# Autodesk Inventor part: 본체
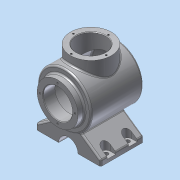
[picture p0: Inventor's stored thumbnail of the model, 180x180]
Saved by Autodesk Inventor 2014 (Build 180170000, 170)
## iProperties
Created: 2017-04
Part Number: 본체
Material: 알루미늄 6061
Document SubType Name: Modeling
Designer: SCD-A15
Density: 2.71 g/cm^3
Appearance: 알루미늄 - 평지
Mass: 1670.64 g
Surface Area: 1066.86 cm^2
Volume: 616.472 cm^3
Author: SCD-A15
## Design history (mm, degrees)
sketch "스케치1"
  geometry: L1 (-60, 0)-(60, 0); L2 (-45, 50)-(46.454, 50); L3 (-48, 47)-(-48, 41); L4 (-51, 38)-(-60, 38); L5 (-60, 38)-(-60, 28); L6 (-38, 37)-(-38, 27); L7 (-35, 40)-(39.903, 40); L8 (-38, 27)-(-59, 27); L9 (-60, 28)-(-59, 27); A1 r 113 centre (-53, 0) between (60, 0) and (49.166, 48.282); A2 r 103 centre (-53, 0) between (50, 0) and (42.69, 38.11); A3 r 3 centre (-35, 37) between (-35, 40) and (-38, 37); A4 r 3 centre (39.903, 37) between (42.69, 38.11) and (39.903, 40); A5 r 3 centre (46.454, 47) between (49.166, 48.282) and (46.454, 50); A6 r 3 centre (-45, 47) between (-45, 50) and (-48, 47); A7 r 3 centre (-51, 41) between (-51, 38) and (-48, 41); 6 further points
  constraints: 18 end point, 16 point on circle, 10 point on line, 10 tangent, 7 centre point, 4 equal radius, 4 parallel, 3 perpendicular, 1 horizontal
  dimensions: "d0" = 120 distance of L1.start L1.end; "d1" = 226 diameter of A1; "d2" = 100 diameter of L2 L1; "d4" = 10 radial gap between concentric circles of A2 A1; "d7" = 60 horizontal distance of point (0, 0) L4.end; "d8" = 22 distance between parallel lines of L5 L6; "d9" = 54 diameter of L8 L1; "d10" = 76 diameter of L4.end L1; "d12" = 108 horizontal distance of point (-48, 50) L1.end; "d13" = 3 radius of A3; "d14" = 1 distance of L5.end point (-60, 27); "d15" = 1 distance of L8.end point (-60, 27) (= d14); "d98" = 80 diameter of L7 L1
revolve "회전1" sketch "스케치1" stored, may be unused: angle "d16" = 90 deg
node "작업 평면1"
sketch "스케치2"
  geometry: C1 r 27 at (-2, 0); C2 r 38 at (-2, 0); 3 further points
  constraints: 2 centre point, 2 coincident, 1 vertical alignment, 2 other
extrude "돌출1" join sketch "스케치2" stored distance "d21" = 10; taper "d22" = 0 deg
extrude "돌출2" cut sketch "스케치2" distance "d23" = 50; taper "d24" = 0 deg
hole "구멍1" sketch "스케치2" diameter "d25" = 3.242; stored, may be unused: countersink angle "d29" = 90 deg, drill point angle "d31" = 118 deg; dims "d26" = 8, "d27" = 4, "d28" = 2, "d30" = 10
sketch "스케치3"
  geometry: L1 (-82, -60)-(-72, -60); L2 (-72, -60)-(-45.101, -21.584); L3 (-72, -60)-(-25.103, -60); L4 (-82, 60)-(-72, 60); L5 (-72, 60)-(-45.101, 21.584); L6 (-72, 60)-(-25.103, 60); L7 (-82, -60)-(-82, -18); L8 (-82, 18)-(-82, 60); A1 r 18 centre (-82, 0) between (-82, -18) and (-82, 18); A2 r 50 centre (0, 0) between (-45.101, 21.584) and (-45.101, -21.584); 1 further point
  constraints: 16 end point, 4 point on circle, 2 centre point, 2 equal length, 2 horizontal, 2 perpendicular, 1 parallel
  dimensions: "d36" = 120 distance of L1.start L4.start; "d38" = 10 distance of L1.start L1.end; "d39" = 55 deg angle of L3 L2; "d40" = 10 distance of L4.start L4.end; "d41" = 55 deg angle of L5 L6; "d42" = 36 diameter of A1; "d43" = 82 distance of point (0, 0) A1.centre
extrude "돌출3" join sketch "스케치3" stored distance "d44" = 80; taper "d45" = 0 deg
node "작업 평면2"
sketch "스케치4"
  geometry: L1 (12, -68)-(12, -78); L2 (12, -78)-(28, -78); L3 (28, -78)-(28, -68); L4 (52, -68)-(52, -78); L5 (52, -78)-(68, -78); L6 (68, -78)-(68, -68); L7 (12, 32)-(12, 42); L8 (12, 42)-(28, 42); L9 (28, 42)-(28, 32); L10 (52, 32)-(52, 42); L11 (52, 42)-(68, 42); L12 (68, 42)-(68, 32); A1 r 8 centre (20, -68) between (28, -68) and (12, -68); A2 r 8 centre (60, -68) between (68, -68) and (52, -68); A3 r 8 centre (60, 32) between (52, 32) and (68, 32); A4 r 8 centre (20, 32) between (12, 32) and (28, 32); 5 further points
  constraints: 24 end point, 8 point on circle, 4 centre point, 4 coincident, 4 perpendicular, 4 tangent, 3 parallel, 1 vertical
  dimensions: "d47" = 16 diameter of A1; "d48" = 16 diameter of A2; "d49" = 16 diameter of A3; "d50" = 16 diameter of A4; "d51" = 40 distance of A2.centre A1.centre; "d52" = 40 distance of A4.centre A3.centre; "d53" = 100 distance of A4.centre A1.centre; "d54" = 100 distance of A3.centre A2.centre; "d55" = 20 horizontal distance of A1.centre point (40, -18); "d56" = 50 vertical distance of point (40, -18) A2.centre; "d57" = 50 vertical distance of point (40, -18) A1.centre; "d58" = 50 vertical distance of point (40, -18) A4.centre; "d59" = 10 distance of L1.start L1.end; "d60" = 16 distance of L1.end L2.end; "d61" = 10 distance of L2.end L3.end; "d62" = 10 distance of L4.start L4.end; "d63" = 16 distance of L4.end L5.end; "d64" = 10 distance of L5.end L6.end; "d65" = 10 distance of L7.start L7.end; "d66" = 16 distance of L7.end L8.end; "d67" = 10 distance of L8.end L9.end; "d68" = 10 distance of L10.start L10.end; "d69" = 16 distance of L10.end L11.end; "d70" = 10 distance of L11.end L12.end
extrude "돌출4" cut sketch "스케치4" distance "d71" = 20; taper "d72" = 0 deg
hole "구멍2" sketch "스케치4" diameter "d73" = 8; stored, may be unused: countersink angle "d77" = 90 deg, drill point angle "d79" = 118 deg; dims "d74" = 8, "d75" = 4, "d76" = 2, "d78" = 10
node "작업 평면3"
sketch "스케치5"
  geometry: 2 further points
  constraints: 1 coincident, 1 other
feature "엠보싱1" sketch "스케치5" dims "d0" = 120, "d1" = 226, "d2" = 100, "d4" = 10, "d7" = 60, "d8" = 22, "d9" = 54, "d10" = 76, "d12" = 108, "d13" = 3, "d14" = 1, "d15" = 1 (= d14), "d81" = 0.5, "d82" = 0, "d98" = 80
fillet "모깎기1" dims "d83" = 3
sketch "스케치6" dims "d84" = 65
  geometry: C1 r 28 at (0, 0) reference; 2 further points
  constraints: 1 coincident, 1 vertical alignment, 2 other
hole "구멍3" sketch "스케치6" at (0, 32.5) diameter "d85" = 3.242; stored, may be unused: countersink angle "d89" = 90 deg, drill point angle "d91" = 118 deg; dims "d86" = 8, "d87" = 4, "d88" = 2, "d90" = 10
chamfer "모따기1" distance "d95" = 1; stored, may be unused: second distance "d96" = 2, angle "d97" = 45 deg
node "솔리드1"
pattern_circular "원형 패턴1" dims angle "d33" = 360 deg
pattern_circular "원형 패턴2" dims angle "d93" = 360 deg
other parameters: "d17" = 65, "d46" = -6
